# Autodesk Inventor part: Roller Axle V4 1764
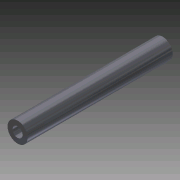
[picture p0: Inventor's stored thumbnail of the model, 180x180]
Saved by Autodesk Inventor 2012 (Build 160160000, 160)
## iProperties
Created: 2007-11
Part Number: Roller Axle V4 1764
Document SubType Name: Modeling
Designer: lwoods
Density: 7.84 g/cm^3
Material: Steel, High Strength Low Alloy
Mass: 10.4976 g
Surface Area: 11.0198 cm^2
Volume: 1.33898 cm^3
Author: lwoods
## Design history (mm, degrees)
sketch "Sketch1"
  geometry: C1 r 3.162 at (-19.585, 0.998)
  constraints: 1 centre point
  dimensions: "d0" = 6.3246 diameter of C1
extrude "Extrusion1" new body sketch "Sketch1" distance "d1" = 45.8724; taper "d2" = 0 deg
sketch "Sketch2"
  geometry: C1 r 3.162 at (0, 0) reference; C2 r 1.6 at (0, 0)
  constraints: 1 centre point, 1 coincident
  dimensions: "d3" = 3.2004 diameter of C2
extrude "Extrusion2" cut sketch "Sketch2" distance "d4" = 6.35; taper "d5" = 0 deg
sketch "Sketch3"
  geometry: C1 r 3.162 at (0, 0) reference; C2 r 1.6 at (0, 0)
  constraints: 1 centre point, 1 coincident
  dimensions: "d6" = 3.2004 diameter of C2
extrude "Extrusion3" cut sketch "Sketch3" distance "d7" = 6.35; taper "d8" = 0 deg
body "Solid1"
